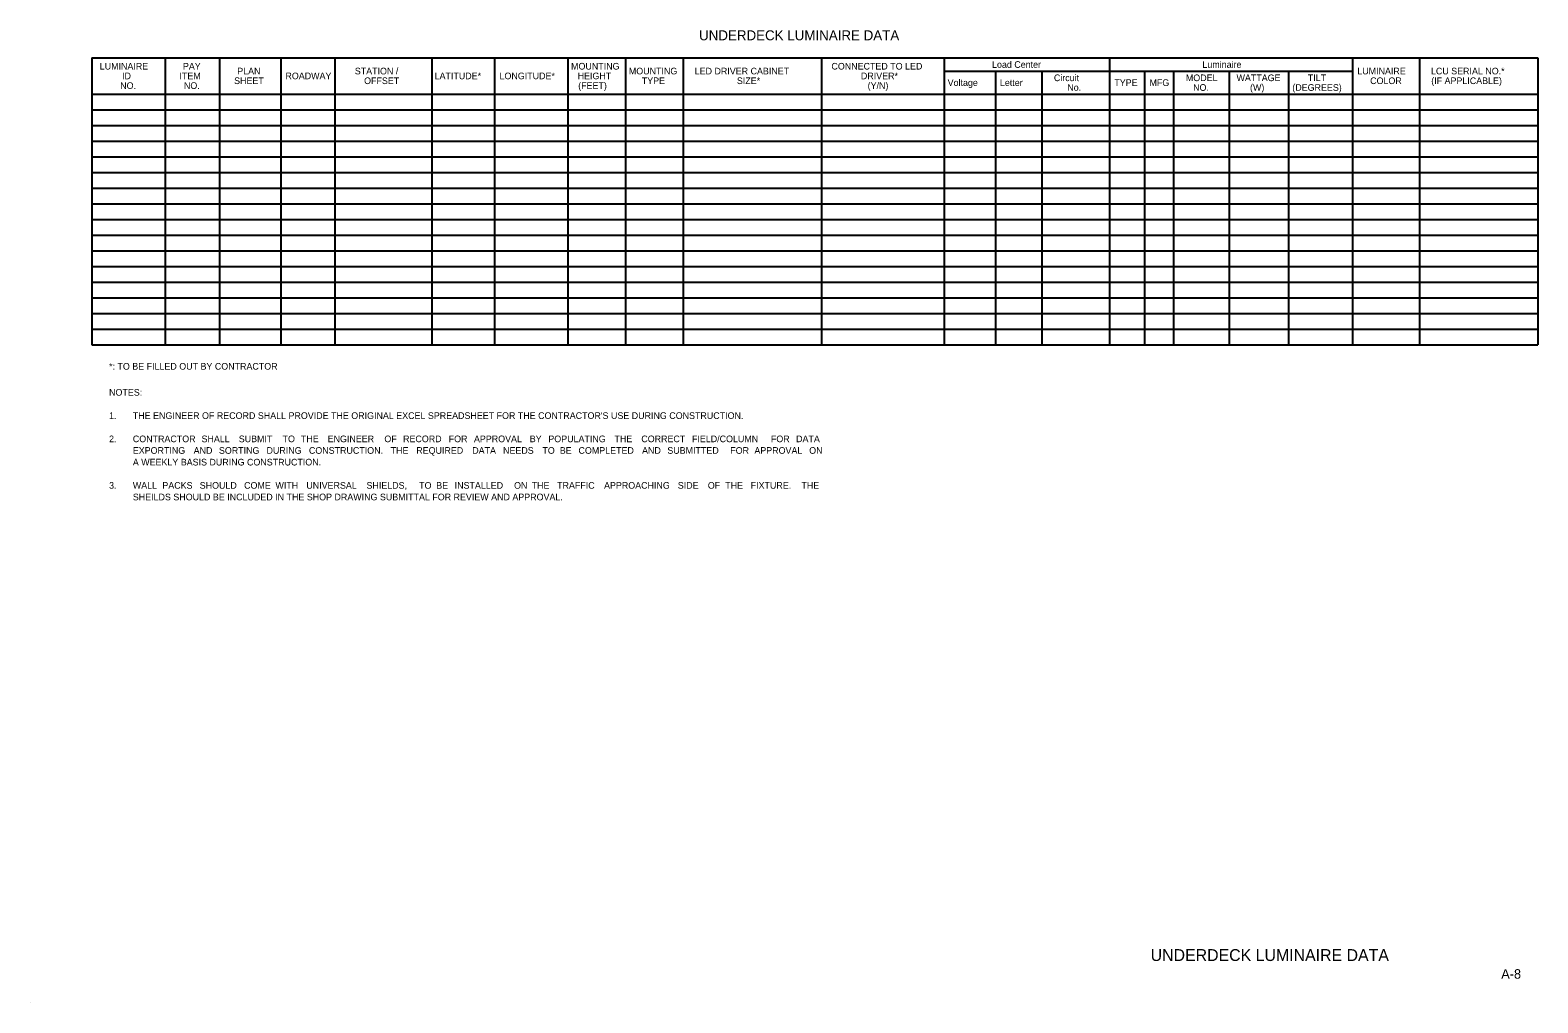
# Model space of a CAD drawing. Extents: x -830028.7 to -830012.8, y 1290283.4 to 1290293.7.
import ezdxf

# ---------------------------------------------------------------- set-up
doc = ezdxf.new("R2010")
doc.units = 0
for name, color, linetype in [('AdhocPoint_dp', 7, 'Continuous'), ('SumBoxBorder_dp', 7, 'Continuous'), ('SumBoxLines_dp', 7, 'Continuous'), ('SumBoxLinesMin_dp', 7, 'Continuous'), ('TextLabel', 7, 'Continuous'), ('TextMisc', 7, 'Continuous'), ('TextNotes', 7, 'Continuous'), ('TextShtNo', 7, 'Continuous')]:
    doc.layers.add(name, color=color, linetype=linetype)

msp = doc.modelspace()

# ---------------------------------------------------------------- linework, layer by layer
at = {"layer": 'AdhocPoint_dp'}
msp.add_line((-830028.694, 1290283.415), (-830028.694, 1290283.415), dxfattribs=at)
at = {"layer": 'SumBoxBorder_dp'}
for p, q in [((-830028.045, 1290293.368), (-830012.827, 1290293.368)), ((-830028.045, 1290293.368), (-830012.827, 1290293.368)), ((-830028.045, 1290293.368), (-830028.045, 1290290.345)), ((-830027.272, 1290293.368), (-830027.272, 1290292.985)), ((-830027.272, 1290293.368), (-830027.272, 1290292.985)), ((-830026.702, 1290293.368), (-830026.702, 1290292.985)), ((-830026.702, 1290293.368), (-830026.702, 1290292.985)), ((-830026.057, 1290293.368), (-830026.057, 1290292.985)), ((-830026.057, 1290293.368), (-830026.057, 1290292.985)), ((-830025.487, 1290293.368), (-830025.487, 1290292.985)), ((-830025.487, 1290293.368), (-830025.487, 1290292.985)), ((-830024.467, 1290293.368), (-830024.467, 1290292.985)), ((-830024.467, 1290293.368), (-830024.467, 1290292.985)), ((-830023.807, 1290293.368), (-830023.807, 1290292.985)), ((-830023.807, 1290293.368), (-830023.807, 1290292.985)), ((-830023.035, 1290293.368), (-830023.035, 1290292.985)), ((-830023.035, 1290293.368), (-830023.035, 1290292.985)), ((-830022.427, 1290293.368), (-830022.427, 1290292.985)), ((-830022.427, 1290293.368), (-830022.427, 1290292.985)), ((-830021.82, 1290293.368), (-830021.82, 1290292.985)), ((-830021.82, 1290293.368), (-830021.82, 1290292.985)), ((-830020.365, 1290293.368), (-830020.365, 1290292.985)), ((-830020.365, 1290293.368), (-830020.365, 1290292.985)), ((-830019.075, 1290293.368), (-830019.075, 1290292.985)), ((-830019.075, 1290293.368), (-830019.075, 1290292.985)), ((-830019.075, 1290293.225), (-830014.777, 1290293.225)), ((-830019.075, 1290293.225), (-830014.777, 1290293.225)), ((-830018.535, 1290293.225), (-830018.535, 1290292.985)), ((-830018.535, 1290293.225), (-830018.535, 1290292.985)), ((-830018.047, 1290293.225), (-830018.047, 1290292.985)), ((-830018.047, 1290293.225), (-830018.047, 1290292.985)), ((-830017.335, 1290293.368), (-830017.335, 1290292.985)), ((-830017.335, 1290293.368), (-830017.335, 1290292.985)), ((-830016.967, 1290293.225), (-830016.967, 1290292.985)), ((-830016.967, 1290293.225), (-830016.967, 1290292.985)), ((-830016.66, 1290293.225), (-830016.66, 1290292.985)), ((-830016.66, 1290293.225), (-830016.66, 1290292.985)), ((-830016.075, 1290293.225), (-830016.075, 1290292.985)), ((-830016.075, 1290293.225), (-830016.075, 1290292.985)), ((-830015.452, 1290293.225), (-830015.452, 1290292.985)), ((-830015.452, 1290293.225), (-830015.452, 1290292.985)), ((-830014.777, 1290293.368), (-830014.777, 1290292.985)), ((-830014.777, 1290293.368), (-830014.777, 1290292.985)), ((-830012.827, 1290293.368), (-830012.827, 1290290.345)), ((-830028.045, 1290292.985), (-830012.827, 1290292.985)), ((-830028.045, 1290292.985), (-830020.365, 1290292.985)), ((-830019.075, 1290292.985), (-830012.827, 1290292.985)), ((-830028.045, 1290290.345), (-830012.827, 1290290.345))]:
    msp.add_line(p, q, dxfattribs=at)
at = {"layer": 'SumBoxLines_dp'}
for p, q in [((-830014.072, 1290293.368), (-830014.072, 1290290.345)), ((-830014.072, 1290293.368), (-830014.072, 1290290.345)), ((-830027.272, 1290292.985), (-830027.272, 1290290.345)), ((-830027.272, 1290292.985), (-830027.272, 1290290.345)), ((-830026.702, 1290292.985), (-830026.702, 1290290.345)), ((-830026.702, 1290292.985), (-830026.702, 1290290.345)), ((-830026.057, 1290292.985), (-830026.057, 1290290.345)), ((-830026.057, 1290292.985), (-830026.057, 1290290.345)), ((-830025.487, 1290292.985), (-830025.487, 1290290.345)), ((-830025.487, 1290292.985), (-830025.487, 1290290.345)), ((-830024.467, 1290292.985), (-830024.467, 1290290.345)), ((-830024.467, 1290292.985), (-830024.467, 1290290.345)), ((-830023.807, 1290292.985), (-830023.807, 1290290.345)), ((-830023.807, 1290292.985), (-830023.807, 1290290.345)), ((-830023.035, 1290292.985), (-830023.035, 1290290.345)), ((-830023.035, 1290292.985), (-830023.035, 1290290.345)), ((-830022.427, 1290292.985), (-830022.427, 1290290.345)), ((-830022.427, 1290292.985), (-830022.427, 1290290.345)), ((-830021.82, 1290292.985), (-830021.82, 1290290.345)), ((-830021.82, 1290292.985), (-830021.82, 1290290.345)), ((-830020.365, 1290292.985), (-830020.365, 1290290.345)), ((-830020.365, 1290292.985), (-830020.365, 1290290.345)), ((-830019.075, 1290292.985), (-830019.075, 1290290.345)), ((-830019.075, 1290292.985), (-830019.075, 1290290.345)), ((-830018.535, 1290292.985), (-830018.535, 1290290.345)), ((-830018.535, 1290292.985), (-830018.535, 1290290.345)), ((-830018.047, 1290292.985), (-830018.047, 1290290.345)), ((-830018.047, 1290292.985), (-830018.047, 1290290.345)), ((-830017.335, 1290292.985), (-830017.335, 1290290.345)), ((-830017.335, 1290292.985), (-830017.335, 1290290.345)), ((-830016.967, 1290292.985), (-830016.967, 1290290.345)), ((-830016.967, 1290292.985), (-830016.967, 1290290.345)), ((-830016.66, 1290292.985), (-830016.66, 1290290.345)), ((-830016.66, 1290292.985), (-830016.66, 1290290.345)), ((-830016.075, 1290292.985), (-830016.075, 1290290.345)), ((-830016.075, 1290292.985), (-830016.075, 1290290.345)), ((-830015.452, 1290292.985), (-830015.452, 1290290.345)), ((-830015.452, 1290292.985), (-830015.452, 1290290.345)), ((-830014.777, 1290292.985), (-830014.777, 1290290.345)), ((-830014.777, 1290292.985), (-830014.777, 1290290.345))]:
    msp.add_line(p, q, dxfattribs=at)
at = {"layer": 'SumBoxLinesMin_dp'}
for p, q in [((-830020.365, 1290292.985), (-830019.075, 1290292.985)), ((-830028.045, 1290292.82), (-830012.827, 1290292.82)), ((-830028.045, 1290292.82), (-830012.827, 1290292.82)), ((-830028.045, 1290292.655), (-830012.827, 1290292.655)), ((-830028.045, 1290292.655), (-830012.827, 1290292.655)), ((-830028.045, 1290292.49), (-830012.827, 1290292.49)), ((-830028.045, 1290292.49), (-830012.827, 1290292.49)), ((-830028.045, 1290292.325), (-830012.827, 1290292.325)), ((-830028.045, 1290292.325), (-830012.827, 1290292.325)), ((-830028.045, 1290292.16), (-830012.827, 1290292.16)), ((-830028.045, 1290292.16), (-830012.827, 1290292.16)), ((-830028.045, 1290291.995), (-830012.827, 1290291.995)), ((-830028.045, 1290291.995), (-830012.827, 1290291.995)), ((-830028.045, 1290291.83), (-830012.827, 1290291.83)), ((-830028.045, 1290291.83), (-830012.827, 1290291.83)), ((-830028.045, 1290291.665), (-830012.827, 1290291.665)), ((-830028.045, 1290291.665), (-830012.827, 1290291.665)), ((-830028.045, 1290291.5), (-830012.827, 1290291.5)), ((-830028.045, 1290291.335), (-830012.827, 1290291.335)), ((-830028.045, 1290291.17), (-830012.827, 1290291.17)), ((-830028.045, 1290291.005), (-830012.827, 1290291.005)), ((-830028.045, 1290290.84), (-830012.827, 1290290.84)), ((-830028.045, 1290290.675), (-830012.827, 1290290.675)), ((-830028.045, 1290290.51), (-830012.827, 1290290.51))]:
    msp.add_line(p, q, dxfattribs=at)

# ---------------------------------------------------------------- texts
at = {"layer": 'TextLabel'}
for s, height, p in [('UNDERDECK LUMINAIRE DATA', 0.105, (-830021.654, 1290293.551)), ('LUMINAIRE', 0.07, (-830027.961, 1290293.243)), ('PAY', 0.07, (-830027.086, 1290293.243)), ('PLAN', 0.07, (-830026.514, 1290293.192)), ('STATION /', 0.07, (-830025.277, 1290293.192)), ('MOUNTING', 0.07, (-830023.001, 1290293.243)), ('MOUNTING', 0.07, (-830022.393, 1290293.192)), ('LED DRIVER CABINET', 0.07, (-830021.7, 1290293.192)), ('CONNECTED TO LED', 0.07, (-830020.261, 1290293.243)), ('Load Center', 0.07, (-830018.571, 1290293.261)), ('Luminaire', 0.07, (-830016.357, 1290293.261)), ('LUMINAIRE', 0.07, (-830014.727, 1290293.192)), ('LCU SERIAL NO.*', 0.07, (-830013.952, 1290293.192)), ('NO.', 0.07, (-830027.746, 1290293.039)), ('ID', 0.07, (-830027.726, 1290293.141)), ('ITEM', 0.07, (-830027.122, 1290293.141)), ('NO.', 0.07, (-830027.075, 1290293.039)), ('SHEET', 0.07, (-830026.547, 1290293.09)), ('ROADWAY', 0.07, (-830026.007, 1290293.141)), ('OFFSET', 0.07, (-830025.179, 1290293.09)), ('LATITUDE*', 0.07, (-830024.437, 1290293.141)), ('LONGITUDE*', 0.07, (-830023.754, 1290293.141)), ('HEIGHT', 0.07, (-830022.932, 1290293.141)), ('(FEET)', 0.07, (-830022.926, 1290293.039)), ('TYPE', 0.07, (-830022.257, 1290293.09)), ('SIZE*', 0.07, (-830021.256, 1290293.09)), ('DRIVER*', 0.07, (-830019.951, 1290293.141)), ('(Y/N)', 0.07, (-830019.88, 1290293.039)), ('Voltage', 0.07, (-830019.038, 1290293.07)), ('Letter', 0.07, (-830018.488, 1290293.07)), ('Circuit', 0.07, (-830017.92, 1290293.121)), ('No.', 0.07, (-830017.779, 1290293.019)), ('TYPE', 0.07, (-830017.284, 1290293.07)), ('MFG', 0.07, (-830016.914, 1290293.07)), ('MODEL', 0.07, (-830016.531, 1290293.121)), ('NO.', 0.07, (-830016.455, 1290293.019)), ('WATTAGE', 0.07, (-830015.998, 1290293.121)), ('(W)', 0.07, (-830015.856, 1290293.019)), ('(DEGREES)', 0.07, (-830015.411, 1290293.019)), ('TILT', 0.07, (-830015.248, 1290293.121)), ('COLOR', 0.07, (-830014.592, 1290293.09)), ('(IF APPLICABLE)', 0.07, (-830013.949, 1290293.09))]:
    msp.add_text(s, height=height, dxfattribs=at).set_placement(p)
at = {"layer": 'TextMisc'}
msp.add_text('UNDERDECK LUMINAIRE DATA ', height=0.125, dxfattribs=at).set_placement((-830016.902, 1290283.856))
at = {"layer": 'TextNotes'}
for s, p in [('*: TO BE FILLED OUT BY CONTRACTOR', (-830027.863, 1290290.083)), ('NOTES:', (-830027.863, 1290289.809)), ('1.', (-830027.863, 1290289.564)), ("THE ENGINEER OF RECORD SHALL PROVIDE THE ORIGINAL EXCEL SPREADSHEET FOR THE CONTRACTOR'S USE DURING CONSTRUCTION.", (-830027.613, 1290289.564)), ('2.', (-830027.863, 1290289.319)), ('CONTRACTOR ', (-830027.613, 1290289.319)), ('EXPORTING ', (-830027.613, 1290289.197)), ('AND ', (-830026.973, 1290289.197)), ('SHALL ', (-830026.89, 1290289.319)), ('SORTING ', (-830026.707, 1290289.197)), ('SUBMIT ', (-830026.498, 1290289.319)), ('DURING ', (-830026.206, 1290289.197)), ('TO ', (-830026.037, 1290289.319)), ('THE ', (-830025.844, 1290289.319)), ('CONSTRUCTION. ', (-830025.76, 1290289.197)), ('ENGINEER ', (-830025.563, 1290289.319)), ('OF ', (-830024.966, 1290289.319)), ('THE ', (-830024.9, 1290289.197)), ('RECORD ', (-830024.769, 1290289.319)), ('REQUIRED ', (-830024.63, 1290289.197)), ('FOR ', (-830024.289, 1290289.319)), ('DATA ', (-830024.041, 1290289.197)), ('APPROVAL ', (-830024.023, 1290289.319)), ('NEEDS ', (-830023.717, 1290289.197)), ('BY ', (-830023.436, 1290289.319)), ('TO ', (-830023.303, 1290289.197)), ('POPULATING ', (-830023.24, 1290289.319)), ('BE ', (-830023.12, 1290289.197)), ('COMPLETED ', (-830022.923, 1290289.197)), ('THE ', (-830022.544, 1290289.319)), ('CORRECT ', (-830022.262, 1290289.319)), ('AND ', (-830022.254, 1290289.197)), ('SUBMITTED ', (-830021.988, 1290289.197)), ('FIELD/COLUMN ', (-830021.729, 1290289.319)), ('FOR ', (-830021.326, 1290289.197)), ('APPROVAL ', (-830021.072, 1290289.197)), ('FOR ', (-830020.898, 1290289.319)), ('DATA ', (-830020.633, 1290289.319)), ('ON ', (-830020.495, 1290289.197)), ('A WEEKLY BASIS DURING CONSTRUCTION. ', (-830027.613, 1290289.074)), ('3.', (-830027.863, 1290288.829)), ('WALL ', (-830027.613, 1290288.829)), ('SHEILDS SHOULD BE INCLUDED IN THE SHOP DRAWING SUBMITTAL FOR REVIEW AND APPROVAL.', (-830027.613, 1290288.707)), ('PACKS ', (-830027.302, 1290288.829)), ('SHOULD ', (-830026.909, 1290288.829)), ('COME ', (-830026.442, 1290288.829)), ('WITH ', (-830026.112, 1290288.829)), ('UNIVERSAL ', (-830025.787, 1290288.829)), ('SHIELDS, ', (-830025.154, 1290288.829)), ('TO ', (-830024.6, 1290288.829)), ('BE ', (-830024.42, 1290288.829)), ('INSTALLED ', (-830024.226, 1290288.829)), ('ON ', (-830023.601, 1290288.829)), ('THE ', (-830023.416, 1290288.829)), ('TRAFFIC ', (-830023.148, 1290288.829)), ('APPROACHING ', (-830022.654, 1290288.829)), ('SIDE ', (-830021.878, 1290288.829)), ('OF ', (-830021.562, 1290288.829)), ('THE ', (-830021.379, 1290288.829)), ('FIXTURE. ', (-830021.111, 1290288.829)), ('THE ', (-830020.577, 1290288.829))]:
    msp.add_text(s, height=0.07, dxfattribs=at).set_placement(p)
at = {"layer": 'TextShtNo'}
msp.add_text('A-8', height=0.1, dxfattribs=at).set_placement((-830013.212, 1290283.67))

doc.saveas('drawing.dxf')
